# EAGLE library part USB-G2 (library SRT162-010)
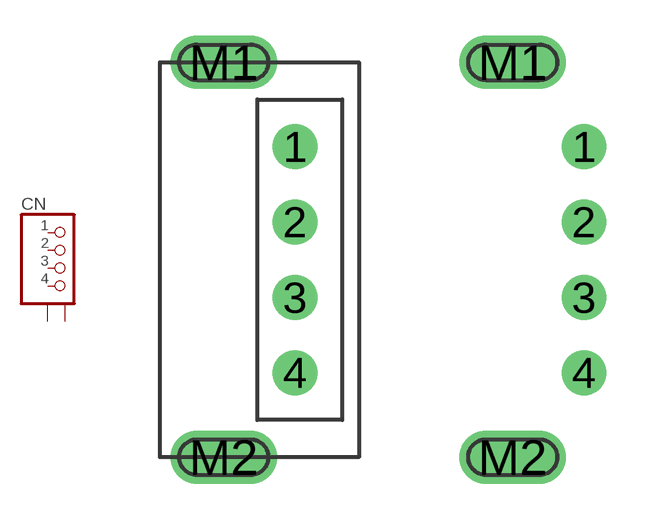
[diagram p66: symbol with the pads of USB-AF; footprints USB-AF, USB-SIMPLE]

Designator prefix CN

## USB-G2  [USB-AF]
1  1_VBUS  pas
2  2_D-  pas
3  3_D+  pas
4  4_GND  pas
M1  GND1  pas
M2  GND2  pas

## USB-G2SIMPLE  [USB-SIMPLE]
Pads as for USB-AF

## Footprint USB-AF (pad centres in mm)
drill 1 round: 1 0,3.81; 2 0,1.27; 3 0,-1.27; 4 0,-3.81
drill 1.2 long: M1 -2.4,6.65; M2 -2.4,-6.65

## Footprint USB-SIMPLE (pad centres in mm)
drill 1 round: 1 0,3.81; 2 0,1.27; 3 0,-1.27; 4 0,-3.81
drill 1.2 long: M1 -2.4,6.65; M2 -2.4,-6.65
